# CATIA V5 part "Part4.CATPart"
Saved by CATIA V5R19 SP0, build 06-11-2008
Part number: Guide
Bounding box of the stored display mesh (mm): x -5 to 5, y -5 to 5, z -25 to 25
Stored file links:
  D:\Shriniwas\v5_r19\c16_CAT_v5r19\c16_Part\Cam_Follower_msm_trial\Part4.CATPart
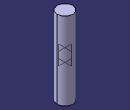
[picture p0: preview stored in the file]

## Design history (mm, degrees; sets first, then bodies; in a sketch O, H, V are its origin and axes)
Body1 (main body)
  Sketch1 on xy-plane, origin (0, 0, 0), H (1, 0, 0), V (0, 1, 0)
    circle A1 centre (0, 0) radius 5
    radius A1 = 5
  Pad1: profile Sketch1, direction (0, 0, 1), length 25, mirrored extent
